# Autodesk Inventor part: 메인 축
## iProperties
Created: 2012-05
Part Number: 메인 축
Document SubType Name: 모델링
Designer: SeoGD™
Mass: 21.4462 g
Surface Area: 72.5109 cm^2
Volume: 21.4462 cm^3
Density: 1 g/cm^3
변환 표준: STEP AP214IS
파일 이름: C:\Users\SeoGD\Desktop\?쒗뿕\硫붿씤 異?.stp
전처리기: Build: 253, Release: 2010 SP1 - Date: Wed 07/29/2009
전송 단위: 밀리미터
불확실성: 0.01
Author: SeoGD™
